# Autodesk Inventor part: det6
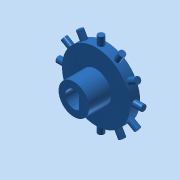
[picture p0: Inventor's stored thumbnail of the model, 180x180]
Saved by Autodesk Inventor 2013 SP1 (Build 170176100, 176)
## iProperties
Created: 2016-04
Part Number: det6
Material: Пластик АБС
Document SubType Name: Modeling
Designer: Кравец
Density: 1 g/cm^3
Author: Кравец
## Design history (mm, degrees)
sketch "Эскиз1"
  geometry: L1 (-1.5, 2)-(-1.5, -2); C1 r 4.5 at (0, 0); A1 r 2.5 centre (0, 0) between (-1.5, 2) and (-1.5, -2); 1 further point
  constraints: 2 centre point, 2 end point, 2 point on circle, 1 coincident, 1 concentric, 1 vertical
  dimensions: "d0" = 5 diameter of A1; "d2" = 1.5 distance from line of point (0, 0) L1; "d3" = 9 diameter of C1
extrude "Выдавливание1" new body sketch "Эскиз1" distance "d4" = 9.5; taper "d5" = 0 deg
sketch "Эскиз2"
  geometry: C1 r 4.5 at (0, 0) reference; C2 r 10 at (0, 0)
  constraints: 1 centre point, 1 coincident
  dimensions: "d6" = 20 diameter of C2
extrude "Выдавливание2" join sketch "Эскиз2" distance "d8" = 3; taper "d9" = 0 deg
node "РабПлоскость1"
sketch "Эскиз3"
  geometry: L1 (0, -10)-(0, 10) reference; L2 (0, 0)-(-3.49, 0); C1 r 0.9 at (1.5, 0); 1 further point
  constraints: 2 end point, 1 centre point, 1 midpoint, 1 perpendicular, 1 point on line
  dimensions: "d10" = 1.8 diameter of C1; "d12" = 1.5 distance from line of C1.centre L1
extrude "Выдавливание3" join sketch "Эскиз3" distance "d13" = 2; taper "d14" = 0 deg; dims "d15" = 2.5, "d16" = 0
pattern_circular "Круговой массив1" dims angle "d18" = 360 deg
node "Твердое тело1"
